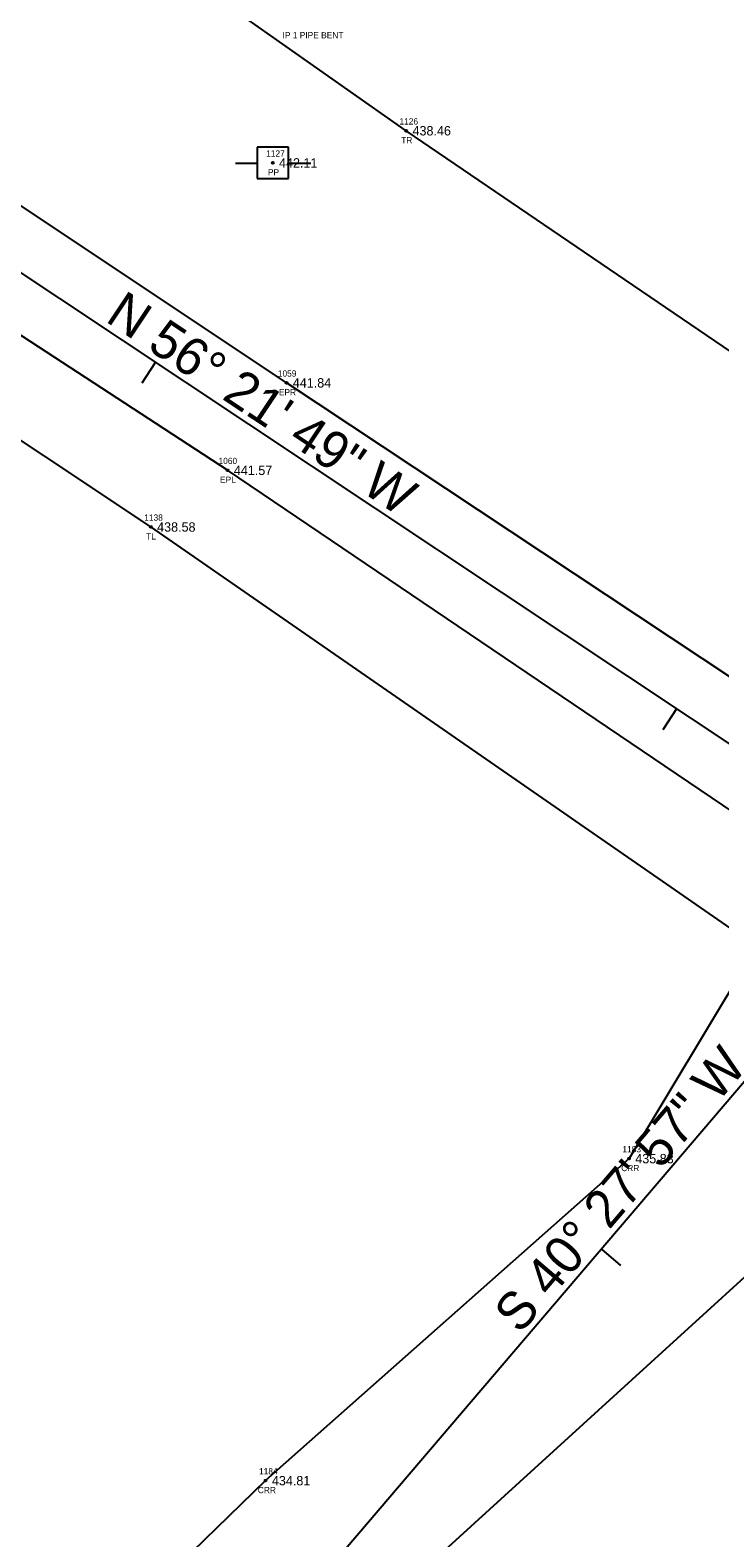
# Model space of a CAD drawing. Extents: x 1796360 to 1799195, y 895805 to 899730.
# Drawn here: x 1798239.7 to 1798350, y 896378.1 to 896619.1 of the extents above; entities that cross this region are included whole.
import ezdxf

# ---------------------------------------------------------------- set-up
doc = ezdxf.new("R2010")
doc.units = 0
for name, color, linetype in [('RD_EX_DV_Prop_txCode', 7, 'Continuous'), ('RD_EX_H2O', 7, 'Continuous'), ('RD_EX_H2O_txCode', 7, 'Continuous'), ('RD_EX_Road', 7, 'Continuous'), ('RD_EX_Road_txCode', 7, 'Continuous'), ('RD_EX_TX_H2O_ELEV', 7, 'Continuous'), ('RD_EX_TX_Road_ELEV', 7, 'Continuous'), ('RD_EX_TX_VEG_ELEV', 7, 'Continuous'), ('RD_EX_UT', 7, 'Continuous'), ('RD_EX_UT_txCode', 7, 'Continuous'), ('RD_EX_VEG', 7, 'Continuous'), ('RD_EX_VEG_txCode', 7, 'Continuous'), ('RD_HC_Cl', 7, 'Continuous'), ('RD_HC_Data', 7, 'Continuous'), ('RD_HC_Data_Tic', 7, 'Continuous'), ('RD_HC_Survey_ELEV', 7, 'Continuous'), ('RD_SMD_Locator', 7, 'Continuous')]:
    doc.layers.add(name, color=color, linetype=linetype)

msp = doc.modelspace()

# ---------------------------------------------------------------- linework, layer by layer
at = {"layer": 'RD_EX_H2O'}
for points in [[(1798502.61, 896635.66), (1798452.16, 896551.79), (1798380.86, 896504.02), (1798360.17, 896479.84), (1798335.44, 896438.68), (1798277.37, 896387.2), (1798228.36, 896339.61), (1798175.66, 896278.7), (1798083.83, 896204.11), (1798020.11, 896146.19)], [(1798443.56, 896510.19), (1798406.44, 896491.18), (1798387.57, 896460.96), (1798358.05, 896423.51), (1798298.17, 896368.97), (1798249.86, 896318.72)]]:
    msp.add_lwpolyline(points, dxfattribs=at)
at = {"layer": 'RD_EX_Road'}
for points in [[(1798362.28, 896497.65), (1798367.54, 896505.07), (1798280.71, 896562.69), (1798193.2, 896621.02), (1798104.98, 896679.23), (1798017.88, 896737.39), (1797930.72, 896795.63), (1797844.07, 896853.07), (1797758.11, 896906.97)], [(1798362.28, 896497.65), (1798357.85, 896490.18), (1798271.29, 896548.71), (1798183.2, 896606.17), (1798096.06, 896663.44), (1798006.57, 896721.75), (1797920.8, 896779.27), (1797834.41, 896836.87), (1797748.77, 896891.01)]]:
    msp.add_lwpolyline(points, dxfattribs=at)
at = {"layer": 'RD_EX_UT'}
for p, q in [((1798281, 896600.35), (1798276, 896600.35)), ((1798276, 896600.35), (1798276, 896595.35)), ((1798281, 896595.35), (1798281, 896600.35)), ((1798272.57, 896597.79), (1798276.04, 896597.79)), ((1798280.93, 896597.79), (1798284.57, 896597.79)), ((1798276, 896595.35), (1798281, 896595.35))]:
    msp.add_line(p, q, dxfattribs=at)
at = {"layer": 'RD_EX_VEG'}
for points in [[(1799022.27, 896088.33), (1798937.86, 896144.41), (1798896.41, 896211.5), (1798869.11, 896228.04), (1798778.26, 896284.04), (1798691.36, 896345.52), (1798595.8, 896403.96), (1798518.88, 896459.81), (1798399.83, 896534.95), (1798299.84, 896602.99), (1798218.96, 896659.85), (1798132.31, 896718.94), (1798044.28, 896770.93), (1797952.52, 896827.83), (1797861.07, 896893.41), (1797773.58, 896947.34)], [(1798749.58, 896161.12), (1798777.44, 896196.37), (1798732.29, 896222.81), (1798646.22, 896279.46), (1798558.62, 896342.53), (1798466.43, 896397.6), (1798354.47, 896473.55), (1798259.03, 896539.65), (1798173.88, 896596.34), (1798087.56, 896652.32), (1797997.75, 896711.89), (1797914.4, 896770.94), (1797832.15, 896824.19), (1797742.8, 896880.21)]]:
    msp.add_lwpolyline(points, dxfattribs=at)
at = {"layer": 'RD_HC_Cl'}
for p, q in [((1798362.69, 896497.51), (1798188.2, 896613.6)), ((1798394.12, 896498.17), (1798280.52, 896365))]:
    msp.add_line(p, q, dxfattribs=at)
at = {"layer": 'RD_HC_Data_Tic'}
for p, q in [((1798259.77, 896565.98), (1798257.56, 896562.65)), ((1798343.03, 896510.58), (1798340.82, 896507.25)), ((1798331.02, 896424.2), (1798334.06, 896421.61))]:
    msp.add_line(p, q, dxfattribs=at)
at = {"layer": 'RD_SMD_Locator'}
for centre in [(1798299.84, 896602.99), (1798278.51, 896597.85), (1798280.71, 896562.69), (1798271.29, 896548.71), (1798259.03, 896539.65), (1798335.44, 896438.68), (1798277.37, 896387.2)]:
    msp.add_circle(centre, 0.15, dxfattribs=at)

# ---------------------------------------------------------------- texts
at = {"layer": 'RD_EX_DV_Prop_txCode'}
msp.add_text('IP 1 PIPE BENT', height=1, dxfattribs=at).set_placement((1798280.07, 896617.77))
at = {"layer": 'RD_EX_H2O_txCode'}
for s, p in [('1183', (1798334.38, 896439.68)), ('CRR', (1798334.19, 896436.68)), ('1184', (1798276.31, 896388.2)), ('CRR', (1798276.12, 896385.2))]:
    msp.add_text(s, height=1, dxfattribs=at).set_placement(p)
at = {"layer": 'RD_EX_Road_txCode'}
for s, p in [('1059', (1798279.32, 896563.69)), ('EPR', (1798279.48, 896560.69)), ('1060', (1798269.84, 896549.71)), ('EPL', (1798270.08, 896546.71))]:
    msp.add_text(s, height=1, dxfattribs=at).set_placement(p)
at = {"layer": 'RD_EX_TX_H2O_ELEV'}
for s, p in [('435.83', (1798336.44, 896437.93)), ('434.81', (1798278.37, 896386.45))]:
    msp.add_text(s, height=1.5, dxfattribs=at).set_placement(p)
at = {"layer": 'RD_EX_TX_Road_ELEV'}
for s, p in [('441.84', (1798281.71, 896561.94)), ('441.57', (1798272.29, 896547.96))]:
    msp.add_text(s, height=1.5, dxfattribs=at).set_placement(p)
at = {"layer": 'RD_EX_TX_VEG_ELEV'}
for s, p in [('438.46', (1798300.84, 896602.24)), ('438.58', (1798260.03, 896538.9))]:
    msp.add_text(s, height=1.5, dxfattribs=at).set_placement(p)
at = {"layer": 'RD_EX_UT_txCode'}
for s, p in [('1127', (1798277.45, 896598.85)), ('PP', (1798277.73, 896595.85))]:
    msp.add_text(s, height=1, dxfattribs=at).set_placement(p)
at = {"layer": 'RD_EX_VEG_txCode'}
for s, p in [('1126', (1798298.75, 896603.99)), ('TR', (1798299.04, 896600.99)), ('1138', (1798257.97, 896540.65)), ('TL', (1798258.26, 896537.65))]:
    msp.add_text(s, height=1, dxfattribs=at).set_placement(p)
at = {"layer": 'RD_HC_Data'}
for s, rotation, p in [('N 56%%d 21\' 49" W', 326.3636, (1798251.58, 896572.63)), ('S 40%%d 27\' 57" W', 49.5342, (1798318.01, 896410.49))]:
    msp.add_text(s, height=6, rotation=rotation, dxfattribs=at).set_placement(p)
at = {"layer": 'RD_HC_Survey_ELEV'}
msp.add_text('442.11', height=1.5, dxfattribs=at).set_placement((1798279.51, 896597.1))

doc.saveas('drawing.dxf')
